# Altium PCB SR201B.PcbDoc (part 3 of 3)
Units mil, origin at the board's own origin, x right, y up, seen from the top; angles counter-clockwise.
Board outline 4100 x 3600 mil, 4 copper layers (Top Layer, Signal Layer 1, Signal Layer 2, Bottom Layer), stack 61.6 mil thick; 173 components, 61 nets, 385 pads, 260 vias.
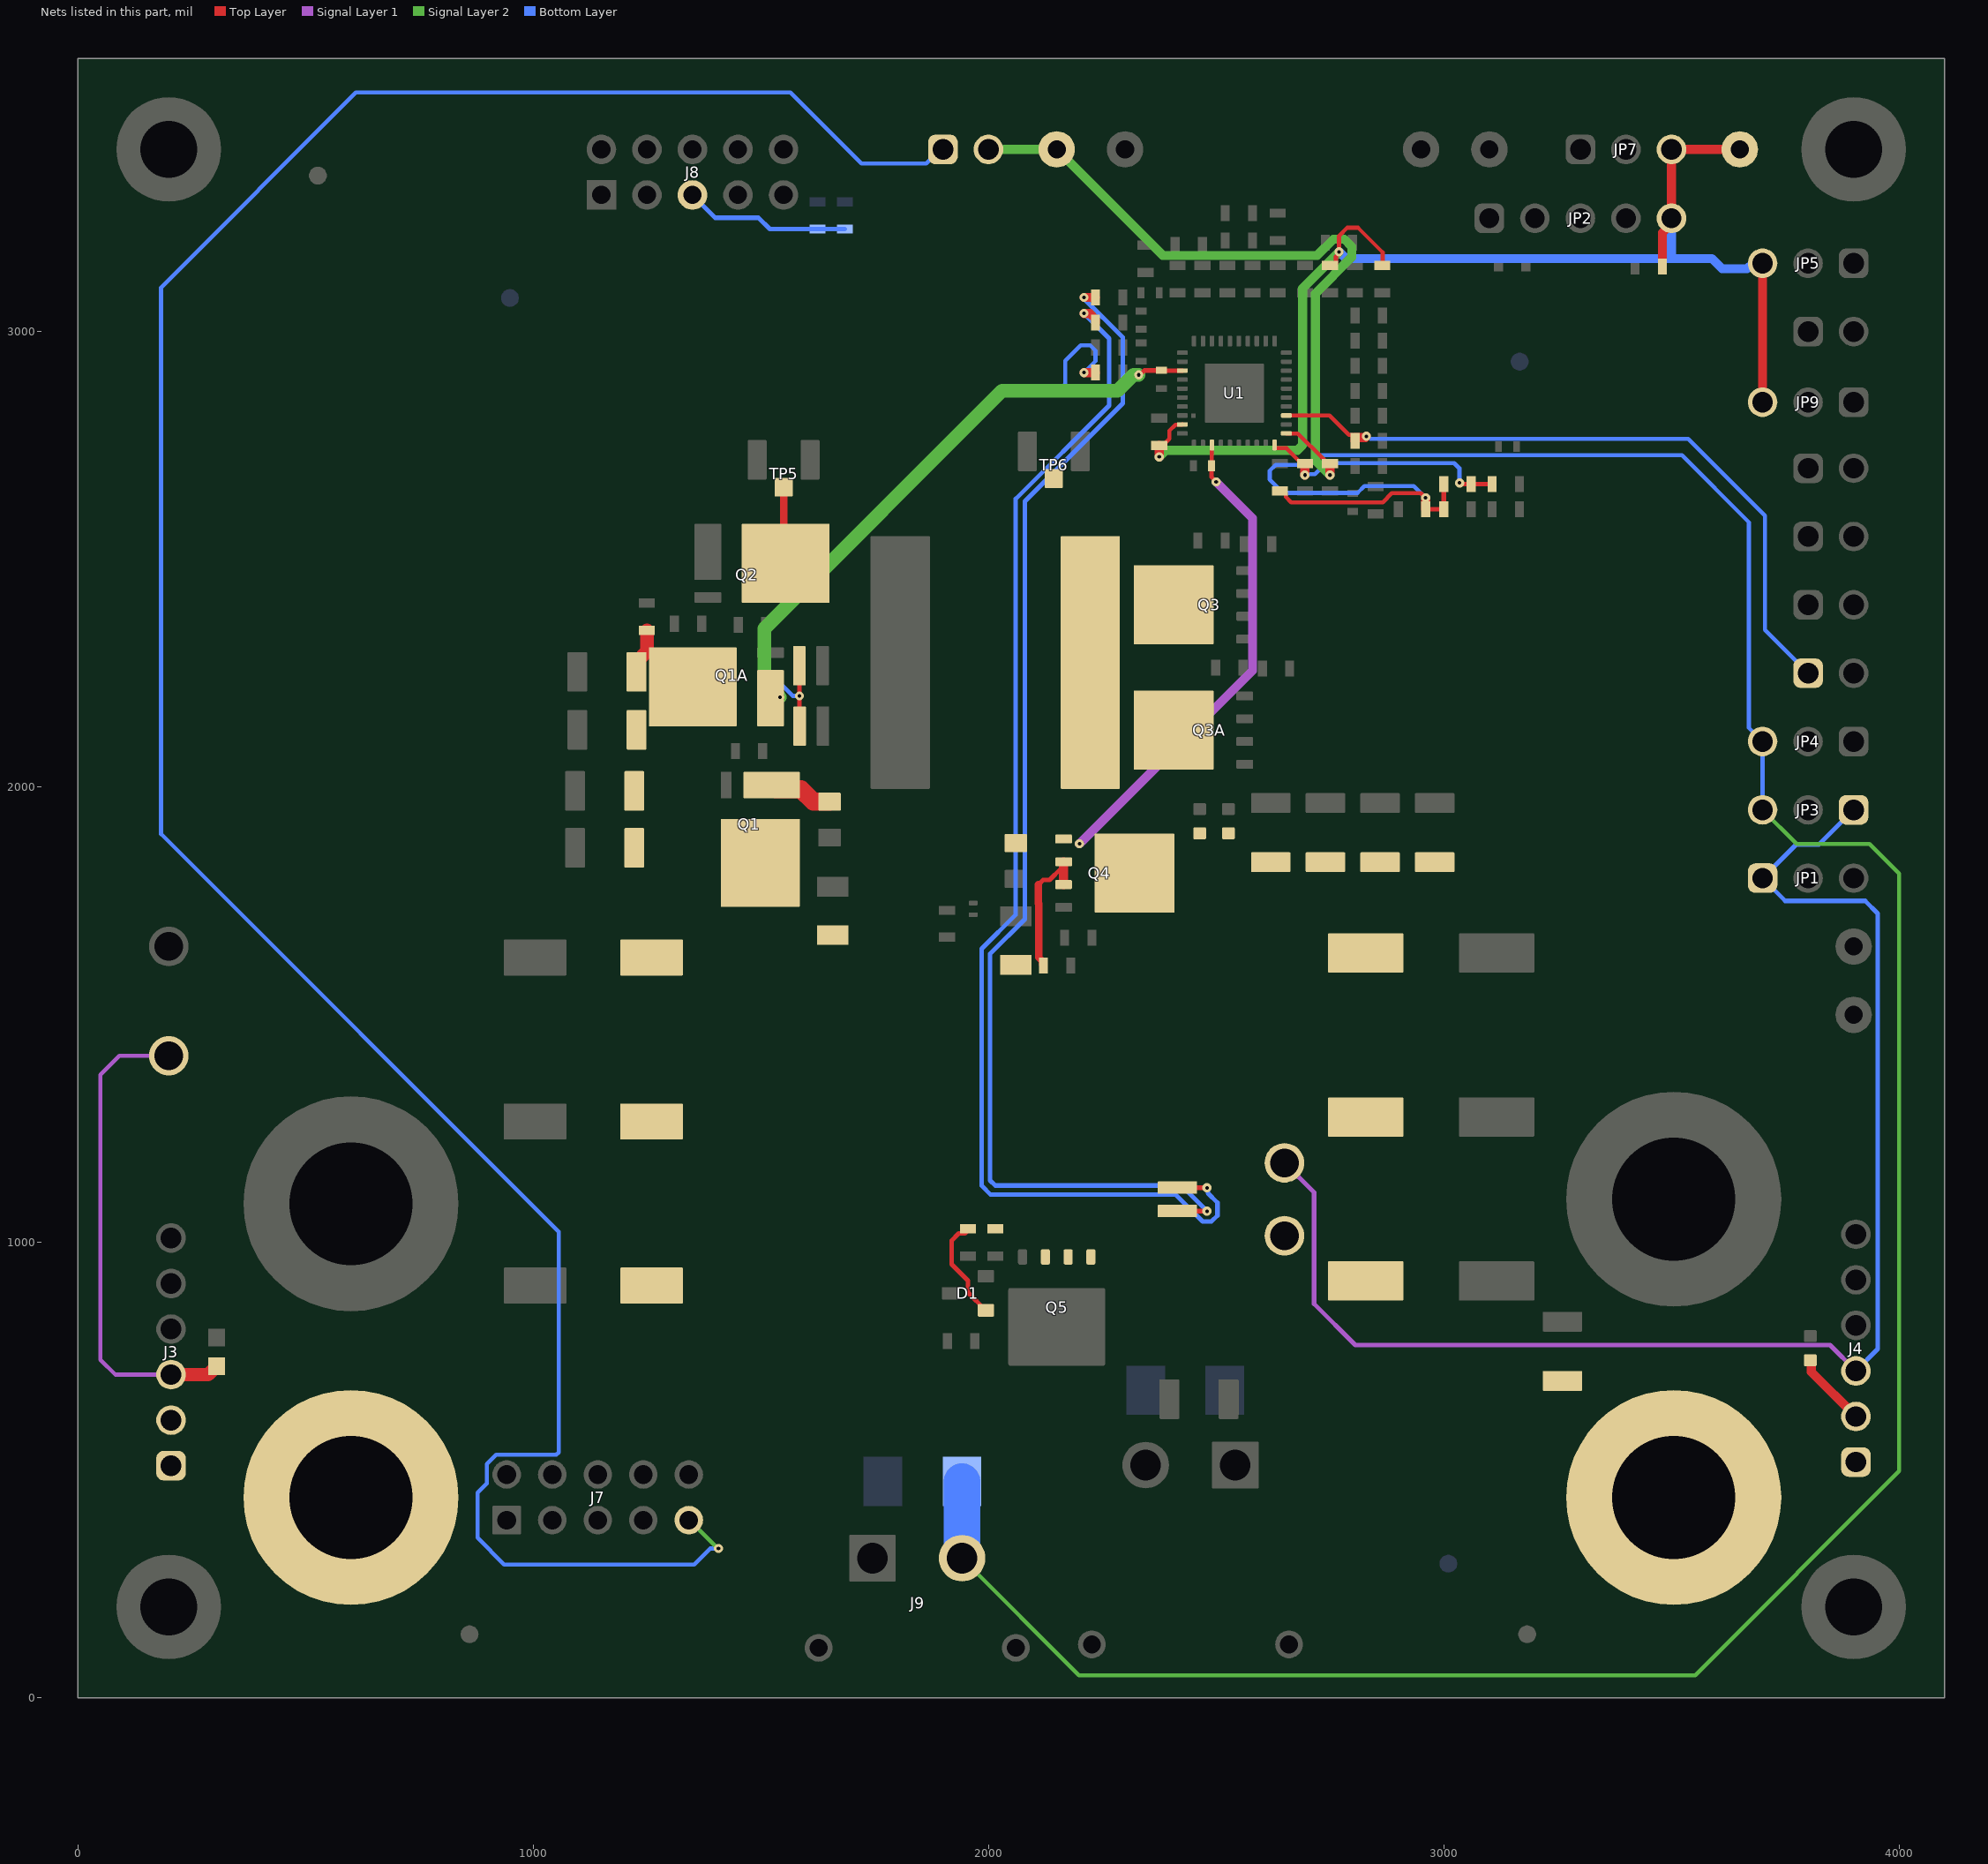
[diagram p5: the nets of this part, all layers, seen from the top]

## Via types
v1: diameter 20, hole 8, Top Layer to Bottom Layer, tented both sides, 239 vias
v2: diameter 19.68, hole 7.87, Top Layer to Bottom Layer, tented both sides, 12 vias
v3: diameter 24, hole 8, Top Layer to Bottom Layer, tented both sides, 7 vias
v4: diameter 34, hole 16, Top Layer to Bottom Layer, tented both sides, 2 vias

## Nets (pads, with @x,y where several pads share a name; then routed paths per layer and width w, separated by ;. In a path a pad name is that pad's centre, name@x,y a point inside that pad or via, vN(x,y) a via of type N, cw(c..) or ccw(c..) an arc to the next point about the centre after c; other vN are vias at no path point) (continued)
SW1: C30.2 C31.1 Q1.1-2-3 Q1A.1-2-3 Q2.5-6-7-8 R4.2 R6.2 R17.2 TP5.1 U1.23 | length 3097.8
  Top Layer w10: Q2.5-6-7-8@1550.29,2495.78 Q2.5-6-7-8@1554.7,2491.37 ; R6.2@1584.71,2266.3 1585,2266.01 v1(1585,2200) 1585,2133.99 R4.2@1585.29,2133.7 ; v1(2330,2905) 2332.71,2905 2342.33,2914.63 2379.63,2914.63 C31.1@2380,2915 2380.71,2914.29 2425.75,2914.29 U1.23@2425.83,2914.21
  Top Layer w16: Q2.5-6-7-8@1550.29,2495.78 TP5.1@1550.32,2658.38
  Top Layer w20: Q1A.1-2-3@1512.09,2197.2 v1(1542.09,2197.2) ; v1(2210,2910) R17.2@2235,2910
  Top Layer w40: Q1.1-2-3@1524.01,2004.4 1533.53,1994.87 1588.22,1994.87 1615.25,1967.84 C30.2@1651.18,1967.84
  Signal Layer 2 w30: v1(1542.09,2197.2) 1507.87,2231.42 1507.87,2347.87 2030,2870 2283.51,2870 2318.51,2905 v1(2330,2905)
  Bottom Layer w9: v1@1584.82,2200.18 1569.82,2200.18 1500,2270 1500,2351.97 2027.09,2879.06 2163.35,2879.06 2168.62,2884.34 2168.62,2935.97 2202.65,2970 2223.45,2970 2235,2958.45 2235,2935 v1(2210,2910)
  Bottom Layer w10: v1@1584.82,2200.18 v1(1585,2200)
SW2: C32.2 C33.1 C42.1 L1.2 Q3.5-6-7-8 Q3A.5-6-7-8 Q4.1 Q4.2 Q4.3 TP6.1 U1.33 | length 1381.8
  Top Layer w9: U1.33@2490.79,2750.83 2490.39,2750.43 2490.39,2705.39 C33.1@2490,2705 2490,2680.35 2500,2670.35 v1(2500,2670)
  Top Layer w10: 2109.81,1785.67 2120.35,1796.21 2134.49,1796.21 2160,1821.72 Q4.2@2160,1835.87
  Top Layer w16: 2109.81,1785.67 2109.81,1744.77 2110.32,1744.25 2110.32,1626.05 2118.85,1617.53 2118.85,1610.03 C42.1@2120.85,1608.03
  Top Layer w20: Q4.3@2165.12,1785.87 Q4.2@2165.12,1835.87
  Signal Layer 1 w20: v1(2200,1875.48) 2580,2255.48 2580,2590 v1(2500,2670)
SYNC: JP6.1 R24.2 U1.3 | length 1536.9
  Top Layer w9: U1.3@2654.17,2815.79 2749.21,2815.79 2792,2773 2799.5,2773 R24.2@2805,2767.5
  Top Layer w20: R24.2@2805,2760 2805,2767.5 2827.5,2767.5 v1(2830,2770)
  Bottom Layer w9: v1(2830,2770) 2832.98,2770 2838.48,2764.5 3536.64,2764.5 3705,2596.14 3705,2345 JP6.1@3800,2250
VBUS: J8.5 R39.2 R40.2 | length 366.1
  Bottom Layer w10: J8.5@1350,3300 1400,3250 1495,3250 1520,3225 R39.2@1625,3225 R40.2@1685,3225
VCC1: C26.2 JP12.2 TP10.1 U1.1 | length 1614.2
  Top Layer w9: U1.1@2654.17,2776.42 2679.48,2776.42 2737,2718.9 2737,2715.5 2742.5,2710 C26.2@2750,2710
  Top Layer w20: v1(2750,2685) C26.2@2750,2710
  Signal Layer 2 w20: JP12.2@2000,3400 TP10.1@2150,3400 2382.87,3167.13 2722.13,3167.13 2757.87,3202.87 2781.55,3202.87 2797.87,3186.55 2797.87,3163.45 2717.87,3083.45 2717.87,2717.13 v1(2750,2685)
VCC1_J: J7.9 JP12.1 | length 5888.6
  Signal Layer 2 w9: J7.9@1342.09,390.59 1343.33,390.59 1405.8,328.13 v1(1407.05,328.13)
  Bottom Layer w9: v1(1407.05,328.13) 1389.11,328.13 1354.11,293.13 936.69,293.13 878.13,351.69 878.13,450.49 898.41,470.78 898.41,513.41 919.26,534.26 1050.73,534.26 1050.98,534.01 1056.25,539.28 1056.25,1023.77 183.13,1896.89 183.13,3096.99 611.14,3525 1565,3525 1721.25,3368.75 1863.48,3368.75 1894.73,3400 JP12.1@1900,3400
VCC2: C27.2 JP2.5 JP5.3 JP7.3 JP9.3 R2.2 R25.2 R36.1 TP9.1 U1.29 | length 2882.7
  Top Layer w9: C27.2@2375,2750 2382.5,2750 2397.37,2764.87 2397.37,2782.44 2410.62,2795.68 2425.41,2795.68 U1.29@2425.83,2796.1 ; R25.2@2750,3145 2757.5,3145 2763,3150.5 2763,3165.02 2770,3172.02 v1(2770,3175) 2770,3210.31 2787.81,3228.13 2811.56,3228.13 2865.82,3173.87 2865.82,3145.82 R36.1@2865,3145
  Top Layer w20: v1(2375,2725) C27.2@2375,2750 ; R2.2@3480,3143 3480,3216.69 3500,3236.69 JP2.5@3500,3248.86 JP7.3@3500,3400 TP9.1@3650,3400 ; JP9.3@3700,2845 JP5.3@3700,3150
  Signal Layer 2 w20: v1(2375,2725) 2389.59,2739.59 2678.28,2739.59 2690,2751.31 2690,3095 v1(2770,3175)
  Bottom Layer w20: v1(2770,3175) 2784.67,3160.33 3493.31,3160.33 ; JP2.5@3500,3248.86 3500,3167.02 3493.31,3160.33 ; JP5.3@3700,3150 3691.4,3141.4 3669.25,3141.4 3665.8,3137.96 3610.9,3137.96 3588.53,3160.33 3493.31,3160.33
VIN: C9.2 C11.1 C12.1 C14.2 C17.2 C18.2 C19.2 C20.2 C40.2 D2.1 J2.1 J3.1 J3.2 J3.3 J9.2 JP3.3 JP4.3 Q1.5-6-7-8 Q1A.5-6-7-8 R7.2 R21.2 R23.2 R35.2 R44.2 TP3.1 | length 7987.6
  Top Layer w9: R35.2@2640,2650 2647.5,2650 2653,2644.5 2653,2637 2665,2625 2866,2625 2886,2645 2949.23,2645 2959.23,2635 v1(2960,2635) ; R21.2@2960,2610 R7.2@3000,2610
  Top Layer w10: R7.2@3000,2610 R44.2@3000,2665
  Top Layer w20: R21.2@2960,2610 v1(2960,2635)
  Top Layer w30: J3.3@205,710 286.5,710 300.31,723.82 301.3,723.82 305,727.52 C11.1@305,728.5 ; C40.2@1227.2,2252.95 1227.2,2274.6 1250,2297.39 C12.1@1250,2344.28
  Signal Layer 1 w9: TP3.1@200,1410 91.83,1410 50,1368.17 50,742.52 82.52,710 J3.3@205,710
  Signal Layer 2 w9: J9.2@1942.09,306.98 2199.07,50 3552,50 4000,498 4000,1810 3935,1875 3775,1875 JP3.3@3700,1950
  Bottom Layer w9: v1(2960,2635) 2934.09,2660.89 2825.72,2660.89 2810.58,2645.75 2647.61,2645.75 2617.63,2675.73 2617.63,2694.27 2630.73,2707.37 2707.37,2707.37 2728.39,2728.39 3522.87,2728.39 3670,2581.25 3670,2130 JP4.3@3700,2100 JP3.3@3700,1950
  Bottom Layer w80: J9.2@1942.09,306.98 D2.1@1942.09,475.59
VIN40: C28.2 R11.1 R44.1 U1.40 | length 570.1
  Top Layer w9: U1.40@2628.58,2750.83 2628.58,2744.46 2629,2744.04 2654.74,2744.04 2654.74,2742.76 2687.5,2710 C28.2@2695,2710
  Top Layer w10: v1@3034.87,2667.5 3037.37,2665 R44.1@3060,2665 R11.1@3103.86,2665
  Top Layer w20: v1(2695,2685) C28.2@2695,2710
  Bottom Layer w9: v1(2695,2685) 2697.1,2687.1 2717.1,2687.1 2741.51,2711.51 3022.71,2711.51
  Bottom Layer w10: 3022.71,2711.01 3034.22,2699.5 3034.22,2668.16 v1@3034.87,2667.5
  other v1: 3034.55,2667.83
VOUT: C1.2 C3.2 C4.2 C8.2 D1.1 J1.1 J4.1 J4.2 Q5.1 Q5.2 Q5.3 R1.2 R3.2 R16.2 TP2.1 | length 3083.2
  Top Layer w10: C1.2@1955,1026.58 1948.38,1019.96 1934.96,1019.96 1919.22,1004.22 1919.22,952.44 1955.16,916.5 1955.16,890.27 D1.1@1994.37,851.06 ; R3.2@2415,1069.41 2415.3,1069.11 2479.7,1069.11 v1(2480,1068.82)
  Top Layer w20: v1(2210,3075) R16.2@2235,3075 ; C8.2@3805,741.5 3807.23,739.27 3807.23,715.84 J4.2@3905,618.07
  Bottom Layer w10: v1(2210,3075) 2210,3072.35 2295,2987.35 2295,2842.36 2080,2627.36 2080,1710 2003.74,1633.74 2003.74,1136.26 2015,1125 2423.82,1125 v1(2480,1068.82)
VOUT1: C5.2 C6.2 C7.2 C10.2 C13.2 C21.2 C22.2 C23.2 J4.3 JP1.1 JP3.1 Q4.5-6-7-8 R3.1 R15.2 R26.2 TP1.1 | length 5941.9
  Top Layer w10: R3.1@2415,1120.59 2415.3,1120.3 2479.7,1120.3 v1(2480,1120)
  Top Layer w20: v1(2210,3040) 2210.37,3039.63 2222.87,3039.63 2235,3027.5 R15.2@2235,3020
  Signal Layer 1 w10: TP1.1@2650,1175 2715,1110 2715,865.49 2805.49,775 3848.07,775 J4.3@3905,718.07
  Bottom Layer w10: v1(2210,3040) 2265,2985 2265,2837.64 2060,2632.64 2060,1719.96 1985,1644.96 1985,1125 2005,1105 2411.47,1105 2470.53,1045.95 2489.47,1045.95 2502.87,1059.34 2502.87,1087.4 2481.91,1108.36 2481.91,1118.09 v1(2480,1120) ; JP3.1@3900,1950 3823.48,1873.48 3773.48,1873.48 JP1.1@3700,1800 3750,1750 3925.43,1750 3952.87,1722.56 3952.87,765.94 J4.3@3905,718.07
pads on no net: FID1.1 FID2.1 FID3.1 FID4.1 FID5.1 FID6.1 H1.1 H2.1 H3.1 H4.1 J8.1 J8.2 J8.3 J8.4 J8.7 J8.8 Q5.9@2056.59,890.08 Q5.9@2097.64,787.91 Q5.9@2097.64,833.19 Q5.9@2097.64,878.46 Q5.9@2150,787.91 Q5.9@2150,827.87 Q5.9@2150,833.19 Q5.9@2150,878.46 Q5.9@2202.36,787.91 Q5.9@2202.36,833.19 Q5.9@2202.36,878.46 Q5.9@2243.41,890.08 U1.26 U1.34 U1.39

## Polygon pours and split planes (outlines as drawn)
VOUT on Top Layer "TOP_LAYER_VOUT_P007" (solid, remove dead copper, pour order 7): 1900.39,1085 1900.39,1005.22 2085.19,1004.83 2085.49,865 2541.87,869.46 2541.87,732.61 2638.84,732.61 2639.53,204.45 ccw(c2679.05,210.5) 2685.1,170.98 2720.69,161.96 2720.69,26.36 4073.49,26.51 4074.51,758.23 2952,758.23 2952,1074.06 ccw(c2941.06,1074.06) 2941.06,1085
GND on Top Layer "TOP_LAYER_GND_P017" (solid, remove dead copper, pour order 17): 0,0 0,3600 4100,3600 4100,0
PPHV on Top Layer "TOP_LAYER_PPHV_P006" (solid, remove dead copper, pour order 6): 2465,920 2023.69,920 2023.69,773.69 1935,685 2050,570 2050,151.18 2049.41,150.59 2050,150 2465,150 2465,440
VOUT1 on Top Layer "TOP_LAYER_VOUT1_P008" (solid, remove dead copper, pour order 8): 2960,1105 2960,1711.64 3035,1786.64 3035,1855.42 2975.42,1915 2284.22,1915 2049.22,1680 1985.32,1680.07 1985.32,1655 1900,1655 1900,1105
AGND on Top Layer "TOP_LAYER_AGND_P000" (solid, remove dead copper, pour order 0): 4100,3600 2250,3600 2250,3300 2465,3085 2465,2790 2535,2790 2640,2685 2640,2650 3525,2650 3610,2565 3610,2155 3855,2155 3855,1900 4100,1900
VIN on Top Layer "TOP_LAYER_VIN_P005" (solid, remove dead copper, pour order 5): 0,750 0,0 1577.09,0 1577.09,150.59 2049.41,150.59 2050,150 2050,570 1880,740 1880,1811.81 1851.81,1840 1555,1840 1555,1872.89 1475,1952.89 1475,2285 1209.4,2285 1180,2255.6 1180,905 1025,750
SW2 on Top Layer "TOP_LAYER_SW2_P004" (solid, remove dead copper, pour order 4): 1875,2620 1924.98,2669.98 2520,2669.98 2520,2055 2420,1955 2420,1925 2320,1925 2300,1905 2300,1762.06 1875,1762.06
NetL1_1 on Top Layer "TOP_LAYER_NETL1_1_P002" (solid, remove dead copper, pour order 2): 1605,2465 1690,2550 1855,2550 1855,1970 1717.22,1970 1605,2082.22
SW1 on Top Layer "TOP_LAYER_SW1_P001" (solid, remove dead copper, pour order 1): 1495,1942.61 1681.16,1942.61 1680.26,1990.99 1605,2066.25 1605,2482.75 1587.75,2500 1462.57,2500 1448.27,2485.7 1448.27,2406.73 1507.5,2347.5 1495,2335
GND on Signal Layer 1 "SIGNAL_LAYER_1_GND_P013" (solid, remove dead copper, pour order 13): 0,0 0,3600 4100,3600 4100,0
AGND on Signal Layer 1 "SIGNAL_LAYER_1_AGND_P010" (solid, remove dead copper, pour order 10): 4100,3600 2250,3600 2250,3300 2465,3085 2465,2790 2535,2790 2640,2685 2640,2650 3525,2650 3610,2565 3610,2155 3855,2155 3855,1900 4100,1900
SW1 on Signal Layer 2 "SIGNAL_LAYER_2_SW1_P012" (solid, remove dead copper, pour order 12): 1542.04,2182.24 1542.04,2227.96 1605,2227.96 1605,2445 1520,2445 1429.74,2354.74 1429.74,2224.04 1471.55,2182.24
GND on Signal Layer 2 "SIGNAL_LAYER_2_GND_P016" (solid, remove dead copper, pour order 16): 0,0 0,3600 4100,3600 4100,0
AGND on Signal Layer 2 "SIGNAL_LAYER_2_AGND_P015" (solid, remove dead copper, pour order 15): 4100,3600 2250,3600 2250,3300 2465,3085 2465,2790 2535,2790 2640,2685 2640,2650 3525,2650 3610,2565 3610,2155 3855,2155 3855,1900 4100,1900
GND on Bottom Layer "BOTTOM_LAYER_GND_P014" (solid, remove dead copper, pour order 14): 0,0 0,3600 4100,3600 4100,0
AGND on Bottom Layer "BOTTOM_LAYER_AGND_P011" (solid, remove dead copper, pour order 11): 4100,3600 2250,3600 2250,3300 2465,3085 2465,2790 2535,2790 2640,2685 2640,2650 3525,2650 3610,2565 3610,2155 3855,2155 3855,1900 4100,1900

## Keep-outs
Keep-Out Layer:
  text ".Layer_Name" at 577,-858.49 h60

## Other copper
Top Layer:
  rectangle net GND: 1577.09,30 2707.09,150.59
  rectangle net GND: 2310,2800 2365,2820
  rectangle net LO2: 2415,2765 2435,2780
  pour cut-out: 1944.14,1759.07 1943.14,1758.07 1943.14,1699.07 1985.24,1699.07 1991.03,1704.85 1991.03,1758.68
  pour cut-out: 235,115 285,165 285,235 235,285 165,285 115,235 115,165 165,115
  pour cut-out: 3935,115 3985,165 3985,235 3935,285 3865,285 3815,235 3815,165 3865,115
  pour cut-out: 3935,3315 3985,3365 3985,3435 3935,3485 3865,3485 3815,3435 3815,3365 3865,3315
  pour cut-out: 235,3315 285,3365 285,3435 235,3485 165,3485 115,3435 115,3365 165,3315
  text ".Layer_Name" at 577,-858.49 h60
Signal Layer 1:
  pour cut-out: 1395,2309.7 1454.7,2309.7 1460,2315 1454.96,2320.04 1395,2320.04
  pour cut-out: 235,115 285,165 285,235 235,285 165,285 115,235 115,165 165,115
  pour cut-out: 3935,115 3985,165 3985,235 3935,285 3865,285 3815,235 3815,165 3865,115
  pour cut-out: 3935,3315 3985,3365 3985,3435 3935,3485 3865,3485 3815,3435 3815,3365 3865,3315
  pour cut-out: 235,3315 285,3365 285,3435 235,3485 165,3485 115,3435 115,3365 165,3315
  text ".Layer_Name" at 577,-858.49 h60
Signal Layer 2:
  pour cut-out: 1530,2460 1618.51,2460 1618.51,2363.51 2070,2815 2379.54,2815 2376.17,2847.81 2365.3,2865 2365.3,2905 2313.72,2940.3 2254.23,2940.3 2237.96,2956.58 2026.58,2956.58
  pour cut-out: 3935,3315 3985,3365 3985,3435 3935,3485 3865,3485 3815,3435 3815,3365 3865,3315
  pour cut-out: 235,115 285,165 285,235 235,285 165,285 115,235 115,165 165,115
  pour cut-out: 235,3315 285,3365 285,3435 235,3485 165,3485 115,3435 115,3365 165,3315
  text ".Layer_Name" at 577,-858.49 h60
Bottom Layer:
  pour cut-out: 1445,2375 1445,2269.52 1514.61,2198.58 1665,2202 1665,2410 2070,2815 2379.54,2815 2376.17,2847.81 2365.3,2865 2365.3,2905 2313.72,2940.3 2254.23,2940.3 2237.96,2956.58 2026.58,2956.58
  pour cut-out: 3935,3315 3985,3365 3985,3435 3935,3485 3865,3485 3815,3435 3815,3365 3865,3315
  pour cut-out: 3935,115 3985,165 3985,235 3935,285 3865,285 3815,235 3815,165 3865,115
  pour cut-out: 235,115 285,165 285,235 235,285 165,285 115,235 115,165 165,115
  pour cut-out: 235,3315 285,3365 285,3435 235,3485 165,3485 115,3435 115,3365 165,3315
  text ".Layer_Name" at 577,-858.49 h60

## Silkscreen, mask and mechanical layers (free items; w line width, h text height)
Top Overlay:
  lines w5: 2218.21,3126 2299,3126 2322,3103 ; 2313,2697 2313,2753 2340,2780 2350,2780 ; 2313,2785 2313,2831 2313,2846 2331,2846 2355,2870 2360,2870 ; 2497,3012 2497,3378 ; 2497,3167.13 2665,3167.13 ; 2665,3060 2665,3167.13 ; 2665,3378 2665,3167.13
  text "VCC1" at 2106,3506 h30
  text "AGND" at 2256,3506 h30
  text "AGND" at 2879.53,3506 h30
  text "COMP" at 3059.45,3506 h30
  text "ILIMCOMP" at 3296,3506 h30
  text "VCC2" at 3596.04,3506 h30
  text "AGND   VCC2" at 3269.96,3311.09 h45
  text "VCC1" at 1906,3287.25 h30
  text "USB2ANY / 5: VBUS / 6: GND / 9: SCL / 10:SDA" at 710,3230 h30
  text "AGND" at 3847.96,3210.73 h45
  text "MODE" at 3522.75,3132.58 h30
  text "FPWM      PSM" at 3660.8,3065.01 h45
  text "CDC" at 3628.03,2984 h30
  text "'.PRJ_Title'" at 284.57,2916.29 h60
  text "AGND" at 3847.96,2906.46 h45
  text "'.PRJ_Number'" at 276.39,2829.07 h40
  text "REV..PCB_Rev" at 518.32,2829.29 h40
  text "SW2" at 1999.49,2827.59 h30
  text "ADDR" at 3508.04,2827.33 h30
  text "SW1" at 1515.65,2811.81 h30
  text "1                0" at 3691.4,2758.91 h45
  text "CFG2" at 3598.04,2671.5 h30
  text "AGND" at 3847.96,2611.46 h45
  text "SCL" at 3628.03,2520 h30
  text "AGND" at 3847.96,2458.71 h45
  text "SDA" at 3628.03,2366.49 h30
  text "AGND" at 3847.96,2311.46 h45
  text "SYNC" at 3598.04,2219 h30
  text "AGND" at 3847.96,2159.53 h45
  text "EN/UVLO" at 3418.06,2076 h30
  text "VIN" at 3669.78,2007.5 h45
  text "AGND" at 3847.96,2007.99 h45
  text "DANGER" at 336.73,1938.83 h70
  text "BIAS" at 3513.03,1927 h30
  text "VIN" at 3670.04,1857 h45
  text "VOUT1" at 3848.04,1857.49 h45
  text "HIGH VOLTAGE" at 131.22,1845.13 h70
  text "VOUT" at 3508.04,1780 h30
  text "PS" at 3670,1710.49 h45
  text "PPHV" at 3848,1710 h45
  text "nRST" at 3720,1641.54 h30
  text "GND" at 84,1606 h30 r90
  text "SS/ATRK" at 3630,1491.79 h30
  text "Max.14A" at 408.35,1484.98 h70
  text "GND" at 3438.35,1426 h50
  text "9-60V" at 408.35,1394.98 h70
  text "VIN" at 84,1366 h30 r90
  text "Max.:" at 3755.47,1306 h35
  text "5A / 180W" at 3756.27,1244.37 h35
  text "5V - 48V" at 3758.06,1180 h35
  text "VOUT1" at 2553.54,1114.27 h30 r90
  text "GND" at 56,1006 h30
  text "GND" at 3966,988.99 h30
  text "VOUT" at 2553.54,955.49 h30 r90
  text "S-" at 88.27,787.65 h30
  text "S-" at 3966,787.54 h30
  text "GND" at 533.35,766 h50
  text "S+" at 88.52,702.22 h30
  text "S+" at 3966,681.98 h30
  text "VOUT" at 3966,500.03 h30
  text "VIN" at 56,487.13 h30
  text "VIN" at 532.52,81 h50
  text "VOUT" at 3413.36,81 h50
  text "Input" at 1743,72.66 h50
  text "Output" at 2327.1,72.66 h50
  text ".Layer_Name" at 577,-858.49 h60
Bottom Overlay:
  text "GND" at 654.02,1426 h50
  text "GND" at 3570.04,1426 h50
  text "VIN" at 636.99,80.01 h50
  text "VOUT" at 3594,80.01 h50
  text ".Layer_Name" at 577,-858.49 h60
Top Paste:
  text ".Layer_Name" at 577,-858.49 h60
Bottom Paste:
  text ".Layer_Name" at 577,-858.49 h60
Top Solder:
  text ".Layer_Name" at 577,-858.49 h60
  text ".Layer_Name" at 577,-858.49 h60
Bottom Solder:
  text ".Layer_Name" at 577,-858.49 h60
Drill Guide:
  text ".Layer_Name" at 577,-858.49 h60
M1 Board Outline:
  the board outline again, w10
  text ".Layer_Name" at 577,-858.49 h60
M2 Board Dimensions:
  rectangle: 0,-275 125,-150
  rectangle: 125,-400 500,-275
  lines w7: 0,-275 1000,-275 ; 125,-400 125,-150 ; 250,-400 250,-150 ; 500,-400 500,-150 ; 750,-400 750,-150 ; 0,-400 1000,-400 1000,-150 0,-150 0,-400
  text ".Layer_Name" at 577,-858.49 h60
M3 3D STEP Top:
  text ".Layer_Name" at 577,-858.49 h60
M4 3D STEP Bottom:
  text ".Layer_Name" at 577,-858.49 h60
M5 Assembly Top:
  lines w10: -292,-930.17 6308,-930.17 ; -292,-726.83 6310,-726.83 ; -292,-523.5 -292,-1133.5 3713,-1133.5 6310,-1133.5 6310,-523.5 -291.5,-523.5 -291.5,-1133.5 1284,-1133.5 ; 2173,-1133.5 2173,-523.5 ; 3440,-726.83 3440,-523.5 ; 4280,-726.83 4280,-523.5 ; 4902,-1140 4902,-937.17
  text "COMPONENTS MARKED 'DNP' SHOULD NOT BE POPULATED." at 1153.5,-318.5 h60
  text "ASSEMBLY VARIANT:" at 1153,-434 h60
  text ".VariantName" at 2189,-434 h60
  text "PCB VIEWED FROM TOP SIDE" at -228.5,-655.67 h60
  text "BOARD #:" at 2248,-655.67 h60
  text ".PRJ_Number" at 2793.5,-655.67 h60
  text "REV:" at 3638,-655.67 h60
  text ".PCB_Rev" at 3929.5,-655.67 h60
  text "SVN REV:" at 4476,-655.67 h60
  text ".VersionControl_RevNumber" at 4982,-655.67 h60
  text "TID #:" at 2248,-859 h60
  text ".TID" at 2793.5,-859 h60
  text "PLOT NAME =" at -228.5,-1064.34 h60
  text ".plot_File_Name" at 577,-1064.34 h60
  text "GENERATED    :" at 2250,-1064.34 h60
  text ".Print_Date" at 3119.5,-1064.34 h60
  text ".Print_Time" at 3848.5,-1064.34 h60
  text "TEXAS INSTRUMENTS" at 5113,-1064.34 h60
M6 Assembly Bottom:
  lines w10: -292.5,-727.33 6309.5,-727.33 ; -290.5,-930.67 6309.5,-930.67 ; 1115.5,-1140.5 1115.5,-937.67 ; 1737.5,-727.33 1737.5,-524 ; 2577.5,-727.33 2577.5,-524 ; 3844.5,-1134 3844.5,-524 ; 4733.5,-1134 6309,-1134 6309,-524 -292.5,-524 -292.5,-1134 2304.5,-1134 6309.5,-1134 6309.5,-524
  text "COMPONENTS MARKED 'DNP' SHOULD NOT BE POPULATED." at 6102,-318 h60
  text ".VariantName" at 5058,-434 h60
  text "ASSEMBLY VARIANT:" at 6097,-434 h60
  text ".VersionControl_RevNumber" at 1035.5,-656.17 h60
  text "SVN REV:" at 1541.5,-656.17 h60
  text ".PCB_Rev" at 2088,-656.17 h60
  text "REV:" at 2379.5,-656.17 h60
  text ".PRJ_Number" at 3224,-656.17 h60
  text "BOARD #:" at 3769.5,-656.17 h60
  text "PCB VIEWED FROM BOTTOM SIDE" at 6246,-656.17 h60
  text ".TID" at 3224,-859.5 h60
  text "TID #:" at 3769.5,-859.5 h60
  text "TEXAS INSTRUMENTS" at 904.5,-1064.84 h60
  text ".Print_Time" at 2169,-1064.84 h60
  text ".Print_Date" at 2898,-1064.84 h60
  text "GENERATED    :" at 3767.5,-1064.84 h60
  text ".plot_File_Name" at 5440.5,-1064.84 h60
  text "PLOT NAME =" at 6246,-1064.84 h60
M9 Title Sheet:
  drawing of 57 lines, arcs and shapes, not listed
  text "1" at 739.84,8036.5 h70
  text "2" at 3235.5,8036.5 h70
  text "3" at 5724.84,8036.5 h70
  text "4" at 8231.51,8036.5 h70
  text "5" at 10730.5,8036.5 h70
  text "6" at 13235.5,8036.5 h70
  text "A" at -416.5,6893.5 h70
  text "A" at 14383.5,6893.5 h70
  text "B" at -416.5,4513.5 h70
  text "B" at 14383.5,4513.5 h70
  text "C" at -416.5,2138.5 h70
  text "C" at 14383.5,2138.5 h70
  text "PROJECT TITLE:" at 11343.5,277.5 h45
  text ".PRJ_Title" at 11393.5,144.17 h70
  text "DESIGNED FOR:" at 11343.5,-23.5 h45
  text ".PRJ_Customer" at 11393.5,-163.5 h70
  text "D" at -416.5,-231.5 h70
  text "D" at 14383.5,-231.5 h70
  text "FILE NAME:" at 11343.5,-323.5 h45
  text ".PCB_File_Name_No_Path" at 11393.5,-443.5 h70
  text "Texas Instruments (TI) and/or its licensors do not warrant the accuracy or completeness of this specification" at 6374,-605.34 h45
  text "ENGINEER:" at 11343.5,-613.5 h45
  text "LAYOUT BY:" at 12848.5,-613.5 h45
  text "or any information contained therein. TI and/or its licensors do not warrant that this design will meet" at 6329.01,-718 h45
  text ".PRJ_Engineer" at 11393.5,-768.49 h70
  text ".PCB_Layout" at 12899,-768.49 h70
  text "the specifications, will be suitable for your application or fit for any particular purpose, or will operate in" at 6329.01,-830.67 h45
  text ".Layer_Name" at 577,-858.49 h60
  text "ALTIUM DESIGNER VERSION:" at 12848.5,-923.5 h45
  text "an implementation. TI and/or its licensors do not warrant that the design is production worthy. You should" at 6329.01,-943.33 h45
  text "completely validate and test your design implementation to confirm the system functionality for your application." at 6374,-1056 h45
  text ".print_Scale" at 11393.5,-1056.83 h70
  text ".Application_BuildNumber" at 12899,-1056.83 h70
  text "1" at 739.84,-1263.5 h70
  text "2" at 3235.5,-1263.5 h70
  text "3" at 5724.84,-1263.5 h70
  text "4" at 8231.51,-1263.5 h70
  text "5" at 10730.5,-1263.5 h70
  text "6" at 13235.5,-1263.5 h70
M10 Fab Notes:
  drawing of 189 lines, arcs and shapes, not listed
  text "DESIGN INFORMATION" at 12382.02,6356.17 h60
  text "MIN. TRACK WIDTH:" at 11737.46,6224.05 h60
  text "9" at 12833.7,6224.05 h60
  text "MIL" at 12988.46,6224.05 h60
  text "7.874" at 12667.32,6102.36 h60
  text "MIN. CLEARANCE:" at 11737.46,6099.92 h60
  text "MIL" at 12988.46,6099.92 h60
  text "MIN. VIA PAD SIZE:" at 11737.46,5975.8 h60
  text "20" at 12803.71,5975.8 h60
  text "MIL" at 12988.46,5975.8 h60
  text "0.05mm (2MIL)" at 12432.46,5845.9 h60
  text "MINIMUM ANNULAR RING" at 11408.23,5837.67 h60
  text "EXTERNAL" at 13140.46,5837.67 h60
  text "PER" at 11608.23,5727.55 h60
  text "IPC-D-275 CLASS 2 LEVEL C" at 11828.23,5727.54 h60
  text "MIL, HOLES" at 13316.46,5627.07 h60
  text "+/-" at 12924,5618.48 h60
  text "+/-" at 13778,5618.48 h60
  text "REGISTRATION TOLERANCES:" at 11408.23,5617.42 h60
  text "METAL" at 12608,5617.42 h60
  text "5" at 13184.2,5617.42 h60
  text "3" at 14017.2,5617.42 h60
  text "MIL" at 14133.46,5617.42 h60
  text "HOLE SIZE TOLERANCE (UNLESS OTHERWISE SPECIFIED):" at 11408.23,5519.1 h60
  text "+/-" at 13778,5516.23 h60
  text "3" at 14017.2,5515.17 h60
  text "MIL" at 14133.46,5515.17 h60
  text "MATERIAL:" at 11333.46,5377.52 h60
  text "FR-4 High Tg" at 12319.9,5249 h60
  text "X" at 12175.46,5241.01 h60
  text "FR-4" at 11754.46,5236.49 h60
  text "OTHER" at 13242.46,5236.49 h60
  text "62 MIL (1.6mm) +/-10%" at 12074.56,5093.46 h60
  text "X" at 11954.46,5091.01 h60
  text "THICKNESS:" at 11408.23,5085.24 h60
  text "OTHER" at 13359.46,5085.24 h60
  text "TOLERANCE:" at 11408.23,4946.92 h60
  text "X" at 12256.46,4946.92 h60
  text "ANSI IPC-6012 TYPE 3 CLASS 2" at 12434.48,4946.92 h60
  text "OTHER +/-" at 12434.46,4802.73 h60
  text "BOW & TWIST:" at 11408.23,4657.54 h60
  text "X" at 12256.46,4657.54 h60
  text "ANSI IPC-6012 TYPE 3 CLASS 2" at 12434.48,4657.54 h60
  text "OTHER +/-" at 12434.46,4510.85 h60
  text "DRILLING:" at 11333.46,4380.23 h60
  text "NC_DRILL FILES" at 13094.46,4275.04 h60
  text "REFERENCE:" at 11408.23,4271.1 h60
  text "X" at 12065.46,4271.01 h60
  text "AS SHOWN" at 12243.46,4271.1 h60
  text "X" at 12966.46,4271.1 h60
  text "OTHER" at 13392.46,4128.85 h60
  text "PTH COPPER THICKNESS:" at 11407.91,4125.32 h60
  text "X" at 12547.14,4125.32 h60
  text "20-30 um" at 12675.14,4125.32 h60
  text "BOARD FINISH:" at 11333.46,3977.73 h60
  text "SILKSCREEN:" at 11488.68,3867.6 h60
  text "X" at 12446.46,3867.6 h60
  text "TOP" at 12563.46,3867.6 h60
  text "X" at 12956.46,3867.6 h60
  text "BOTTOM" at 13074.46,3867.6 h60
  text "SILKSCREEN COLOR:" at 11488.68,3712.41 h60
  text "X" at 12445.46,3712.41 h60
  text "WHITE" at 12563.46,3712.41 h60
  text "OTHER" at 13074.46,3712.41 h60
  text "X" at 12576.46,3568.96 h60
  text "GREEN" at 12694.46,3568.96 h60
  text "OTHER" at 13312.46,3568.96 h60
  text "SOLDER RESIST COLOR:" at 11488.68,3562.1 h60
  text "X" at 12576.46,3414.71 h60
  text "MATTE" at 12694.46,3414.71 h60
  text "SEMI-GLOSS" at 13312,3414.07 h60
  text "IMMERSION GOLD (ENIG)" at 12394.46,3241.94 h60
  text "ENEPIG" at 13732,3234.72 h60
  text "SURFACE FINISH:" at 11333.46,3233.72 h60
  text "X" at 12216.46,3233.72 h60
  text "IMM. TIN/SILVER OR EQUIV" at 11663,3096.4 h60
  text "OTHER" at 13094.46,3092.47 h60
  text "ARRAY/PANEL:" at 11333.46,2937.09 h60
  text "CUT AND TRIM PER M1 BOARD OUTLINE" at 12394.46,2928.87 h60
  text "N.C. ROUTE" at 12394.46,2792.9 h60
  text "X" at 13082.46,2792.9 h60
  text "V. SCORE" at 13260.46,2792.9 h60
  text "CERTIFICATION:" at 11333.46,2663.77 h60
  text "MATERIALS AND WORKMANSHIP FOR ALL PCBS" at 12058.46,2663.77 h60
  text "TO MEET OR EXCEED THE REQUIREMENTS OF:" at 12058.46,2569.71 h60
  text "X" at 11695.97,2441.08 h60
  text "ANSI IPC-A-600F CLASS ->" at 11823.96,2441.08 h60
  text "X" at 13471.97,2441.08 h60
  text "2" at 13581.96,2441.08 h60
  text "1" at 13266.96,2439.58 h60
  text "3" at 13935.96,2439.58 h60
  text "X" at 12507.97,2293.39 h60
  text "RoHS" at 12635.96,2293.39 h60
  text "OTHER" at 13280.36,2293.39 h60
  text "PER ORDER" at 13677.42,2293.39 h60
  text "ALL BOARDS MUST MEET OR EXCEED UL94-V0 REQUIREMENTS." at 11361,2139.57 h60
  text "PCB MUST BEAR THE UL94V-0 UL REGISTERED MATERIAL ID NUMBER" at 11361,2023.5 h60
  text "ADDITIONAL REQUIREMENTS:" at 11333.46,1854.08 h60
  text "MICROSECTION:" at 11408.23,1746.95 h60
  text "YES" at 12313.96,1746.95 h60
  text "REQUIRED" at 13175.46,1602.62 h60
  text "BARE BOARD ELEC. TEST:" at 11408.23,1599.76 h60
  text "NONE" at 12713.96,1599.76 h60
  text "X" at 13057.46,1599.76 h60
  text "PER ORDER" at 13767.46,1599.76 h60
  text "XX MIL VIAS REQUIRE NON-CONDUCTIVE FILL AND PLANARIZE" at 11576.38,1394.82 h59
  text "XX MIL VIAS REQUIRE CONDUCTIVE FILL AND PLANARIZE" at 11584.38,1290.84 h60
  text "OUTER XX MIL TRACES REQUIRE 50 OHM SINGLE-ENDED IMPEDANCE" at 11583.39,1127.46 h58
  text "LAYER 2 & 3 (INNER LAYERS) XX MIL WIDE, XX MIL SPACE / TRACES REQUIRE 100 OHM DIFFERENTIAL IMPEDANCE" at 11575.39,891.74 h60
  text ".Layer_Name" at 577,-858.49 h60
M11 Gerber Information:
  lines w10: -292,-930.17 6308,-930.17 ; -292,-726.83 6310,-726.83 ; -292,-523.5 -292,-1133.5 3713,-1133.5 6310,-1133.5 6310,-523.5 -291.5,-523.5 -291.5,-1133.5 1284,-1133.5 ; 2173,-1133.5 2173,-523.5 ; 3440,-726.83 3440,-523.5 ; 4280,-726.83 4280,-523.5 ; 4902,-1140 4902,-937.17
  text "ALL ARTWORK VIEWED FROM TOP SIDE" at -228.5,-655.67 h60
  text "BOARD #:" at 2248,-655.67 h60
  text ".PRJ_Number" at 2793.5,-655.67 h60
  text "REV:" at 3638,-655.67 h60
  text ".PCB_Rev" at 3929.5,-655.67 h60
  text "SVN REV:" at 4476,-655.67 h60
  text ".VersionControl_RevNumber" at 4982,-655.67 h60
  text "LAYER NAME =" at -228.5,-858.49 h60
  text "TID #:" at 2248,-859 h60
  text ".TID" at 2793.5,-859 h60
  text "PLOT NAME =" at -228.5,-1064.34 h60
  text ".plot_File_Name" at 577,-1064.34 h60
  text "GENERATED    :" at 2250,-1064.34 h60
  text ".Print_Date" at 3119.5,-1064.34 h60
  text ".Print_Time" at 3848.5,-1064.34 h60
  text "TEXAS INSTRUMENTS" at 5113,-1064.34 h60
M12 Stackup:
  drawing of 295 lines, arcs and shapes, not listed
  text "Layer" at 6560.19,7730.01 h60
  text "Name" at 6970.11,7730.01 h60
  text "Material" at 7909.85,7730.01 h60
  text "Thickness" at 8769.62,7730.01 h60
  text "Constant" at 9419.45,7730.01 h60
  text "Board Layer Stack" at 9989.31,7730.01 h60
  text "Top Overlay" at 6970.11,7610.01 h60
  text "Top Solder" at 6970.11,7490.01 h60
  text "Solder Resist" at 7909.85,7490.01 h60
  text "0.40mil" at 8769.62,7490.01 h60
  text "3.5" at 9419.45,7490.01 h60
  text "1" at 6560.19,7370.01 h60
  text "Top Layer" at 6970.11,7370.01 h60
  text "2.80mil" at 8769.62,7370.01 h60
  text "Dielectric 1" at 6970.11,7250.01 h60
  text "FR-4 High Tg" at 7909.85,7250.01 h60
  text "8.00mil" at 8769.62,7250.01 h60
  text "4.2" at 9419.45,7250.01 h60
  text "2" at 6560.19,7130.01 h60
  text "Signal Layer 1" at 6970.11,7130.01 h60
  text "1.40mil" at 8769.62,7130.01 h60
  text "Dielectric 2" at 6970.11,7010.01 h60
  text "FR-4 High Tg" at 7909.85,7010.01 h60
  text "37.20mil" at 8769.62,7010.01 h60
  text "4.2" at 9419.45,7010.01 h60
  text "3" at 6560.19,6890.01 h60
  text "Signal Layer 2" at 6970.11,6890.01 h60
  text "1.40mil" at 8769.62,6890.01 h60
  text "Dielectric 3" at 6970.11,6770.01 h60
  text "FR-4 High Tg" at 7909.85,6770.01 h60
  text "8.00mil" at 8769.62,6770.01 h60
  text "4.2" at 9419.45,6770.01 h60
  text "4" at 6560.19,6650.01 h60
  text "Bottom Layer" at 6970.11,6650.01 h60
  text "2.80mil" at 8769.62,6650.01 h60
  text "Bottom Solder" at 6970.11,6530.01 h60
  text "Solder Resist" at 7909.85,6530.01 h60
  text "0.40mil" at 8769.62,6530.01 h60
  text "3.5" at 9419.45,6530.01 h60
  text "Bottom Overlay" at 6970.11,6410.01 h60
  text "Total board thickness:" at 6560.19,6290.01 h60
  text "62.40mil" at 8769.62,6290.01 h60
  text ".Layer_Name" at 577,-858.49 h60
M13 Component Bodies Top:
  text ".Layer_Name" at 577,-858.49 h60
M14 Component Bodies Bottom:
  text ".Layer_Name" at 577,-858.49 h60
M15 Courtyards Top:
  text ".Layer_Name" at 577,-858.49 h60
M16 Courtyards Bottom:
  text ".Layer_Name" at 577,-858.49 h60
Drill Drawing:
  circle w10: c5953.63,3896.78 r27.59
  circle w10: c5953.63,3648.43 r16.56
  circle w10: c5953.63,3648.43 r27.59
  lines w10: 5926.04,2641.23 5939.83,2641.23 5939.83,2627.43 5967.43,2627.43 5967.43,2641.23 5981.23,2641.23 5981.23,2668.82 5967.43,2668.82 5967.43,2682.62 5939.83,2682.62 5939.83,2668.82 5926.04,2668.82 5926.04,2641.23 ; 5926.04,2765.4 5939.83,2765.4 5953.63,2751.6 5967.43,2765.4 5981.23,2765.4 5967.43,2779.2 5981.23,2793 5967.43,2793 5953.63,2806.79 5939.83,2793 5926.04,2793 5939.83,2779.2 5926.04,2765.4 ; 5926.04,2875.78 5981.23,2875.78 5981.23,2930.97 5926.04,2930.97 5926.04,2875.78 ; 5926.04,2999.96 5953.63,3013.75 5981.23,2999.96 5967.43,3027.55 5981.23,3055.15 5953.63,3041.35 5926.04,3055.15 5939.83,3027.55 5926.04,2999.96 ; 5926.04,3179.32 5981.23,3179.32 5953.63,3124.13 5926.04,3179.32 ; 5926.04,3262.11 5939.83,3262.11 5953.63,3248.31 5967.43,3262.11 5981.23,3262.11 5967.43,3275.9 5981.23,3289.7 5967.43,3289.7 5953.63,3303.5 5939.83,3289.7 5926.04,3289.7 5939.83,3275.9 5926.04,3262.11 ; 5926.04,3400.08 5953.63,3372.48 5981.23,3400.08 5953.63,3427.67 5926.04,3400.08 ; 5926.04,3496.66 5926.04,3510.46 5939.83,3524.26 5926.04,3538.05 5926.04,3551.85 5939.83,3551.85 5953.63,3538.05 5967.43,3551.85 5981.23,3551.85 5981.23,3538.05 5967.43,3524.26 5981.23,3510.46 5981.23,3496.66 5967.43,3496.66 5953.63,3510.46 5939.83,3496.66 5926.04,3496.66 ; 5926.04,3745.01 5981.23,3745.01 5981.23,3800.2 5926.04,3800.2 5926.04,3745.01 ; 5926.04,4048.55 5981.23,4048.55 5953.63,3993.36 5926.04,4048.55 ; 5937.07,2770.92 5945.35,2770.92 5953.63,2762.64 5961.91,2770.92 5970.19,2770.92 5961.91,2779.2 5970.19,2787.48 5961.91,2787.48 5953.63,2795.76 5945.35,2787.48 5937.07,2787.48 5945.35,2779.2 5937.07,2770.92 ; 5937.07,2886.82 5970.19,2886.82 5970.19,2919.93 5937.07,2919.93 5937.07,2886.82 ; 5937.07,4037.52 5970.19,4037.52 5953.63,4004.4 5937.07,4037.52
  lines w12: 5876,2590.18 9030.69,2590.18 ; 5876,4080.29 9030.69,4080.29 ; 6213.72,2466 6213.72,4204.46 ; 6514.99,2466 6514.99,4204.46 ; 7107,2466 7107,4204.46 ; 7366,2466 7366,4204.46 ; 7741.05,2466 7741.05,4204.46 ; 8464.43,2466 8464.43,4204.46 ; 5876,2466 9030.69,2466 9030.69,4204.46 5876,4204.46 5876,2466
  text "Symbol" at 5950.51,4117.54 h72
  text "Count" at 6250.97,4117.54 h72
  text "Hole Size" at 6552.24,4117.54 h72
  text "Plated" at 7144.25,4117.54 h72
  text "Hole Type" at 7403.25,4117.54 h72
  text "Drill Layer Pair" at 7778.3,4117.54 h72
  text "Hole Tolerance" at 8501.68,4117.54 h72
  text "12" at 6250.97,3993.36 h60
  text "7.87mil (0.200mm)" at 6552.24,3993.36 h60
  text "PTH" at 7144.25,3993.36 h60
  text "Round" at 7403.25,3993.36 h60
  text "Top Layer - Bottom Layer" at 7778.3,3993.36 h60
  text "246" at 6250.97,3869.19 h60
  text "8.00mil (0.203mm)" at 6552.24,3869.19 h60
  text "PTH" at 7144.25,3869.19 h60
  text "Round" at 7403.25,3869.19 h60
  text "Top Layer - Bottom Layer" at 7778.3,3869.19 h60
  text "2" at 6250.97,3745.01 h60
  text "16.00mil (0.406mm)" at 6552.24,3745.01 h60
  text "PTH" at 7144.25,3745.01 h60
  text "Round" at 7403.25,3745.01 h60
  text "Top Layer - Bottom Layer" at 7778.3,3745.01 h60
  text "4" at 6250.97,3620.84 h60
  text "39.37mil (1.000mm)" at 6552.24,3620.84 h60
  text "PTH" at 7144.25,3620.84 h60
  text "Round" at 7403.25,3620.84 h60
  text "Top Layer - Bottom Layer" at 7778.3,3620.84 h60
  text "17" at 6250.97,3496.66 h60
  text "40.00mil (1.016mm)" at 6552.24,3496.66 h60
  text "PTH" at 7144.25,3496.66 h60
  text "Round" at 7403.25,3496.66 h60
  text "Top Layer - Bottom Layer" at 7778.3,3496.66 h60
  text "10" at 6250.97,3372.48 h60
  text "40.95mil (1.040mm)" at 6552.24,3372.48 h60
  text "PTH" at 7144.25,3372.48 h60
  text "Round" at 7403.25,3372.48 h60
  text "Top Layer - Bottom Layer" at 7778.3,3372.48 h60
  text "5" at 6250.97,3248.31 h60
  text "43.31mil (1.100mm)" at 6552.24,3248.31 h60
  text "PTH" at 7144.25,3248.31 h60
  text "Round" at 7403.25,3248.31 h60
  text "Top Layer - Bottom Layer" at 7778.3,3248.31 h60
  text "+/-1.97mil" at 8501.68,3248.31 h60
  text "42" at 6250.97,3124.13 h60
  text "45.28mil (1.150mm)" at 6552.24,3124.13 h60
  text "PTH" at 7144.25,3124.13 h60
  text "Round" at 7403.25,3124.13 h60
  text "Top Layer - Bottom Layer" at 7778.3,3124.13 h60
  text "4" at 6250.97,2999.96 h60
  text "63.00mil (1.600mm)" at 6552.24,2999.96 h60
  text "PTH" at 7144.25,2999.96 h60
  text "Round" at 7403.25,2999.96 h60
  text "Top Layer - Bottom Layer" at 7778.3,2999.96 h60
  text "4" at 6250.97,2875.78 h60
  text "66.93mil (1.700mm)" at 6552.24,2875.78 h60
  text "PTH" at 7144.25,2875.78 h60
  text "Round" at 7403.25,2875.78 h60
  text "Top Layer - Bottom Layer" at 7778.3,2875.78 h60
  text "4" at 6250.97,2751.6 h60
  text "125.00mil (3.175mm)" at 6552.24,2751.6 h60
  text "PTH" at 7144.25,2751.6 h60
  text "Round" at 7403.25,2751.6 h60
  text "Top Layer - Bottom Layer" at 7778.3,2751.6 h60
  text "4" at 6250.97,2627.43 h60
  text "270.00mil (6.858mm)" at 6552.24,2627.43 h60
  text "PTH" at 7144.25,2627.43 h60
  text "Round" at 7403.25,2627.43 h60
  text "Top Layer - Bottom Layer" at 7778.3,2627.43 h60
  text "354 Total" at 6250.97,2503.25 h60
  text ".Layer_Name" at 577,-858.49 h60
M17 Embedded Cavity:
  text ".Layer_Name" at 577,-858.49 h60
M18 Embedded Assembly:
  text ".Layer_Name" at 577,-858.49 h60
M19 Embedded Keepout:
  text ".Layer_Name" at 577,-858.49 h60

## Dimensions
0,-400 to 1000,-400 on M2 Board Dimensions
0,3600 to 4100,0 on M2 Board Dimensions
4100,0 to 0,3600 on M2 Board Dimensions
